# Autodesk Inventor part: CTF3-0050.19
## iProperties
Shininess: 64.0
Length Units: 11269
Angle Units: 11279
Time Units: 11290
Mass Units: 11283
Length Display Precision: 3
Angle Display Precision: 2
Compacted: True
Part Number: CTF3-0050.19
Document SubType Name: Modeling
Created: 2004-01
Designer: Lollo
Density: 0.0
Volumn: 0.0
Area: 0.0
PropertySet Name: Model Information
Control State: 0
Master: False
Checked Out: False
Author: Lollo
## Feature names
1. Estrusione1 [Extrusion]
2. Foro1 [Hole]
3. Smusso1 [Chamfer]
4. Smusso2 [Chamfer]
5. Smusso3 [Chamfer]
